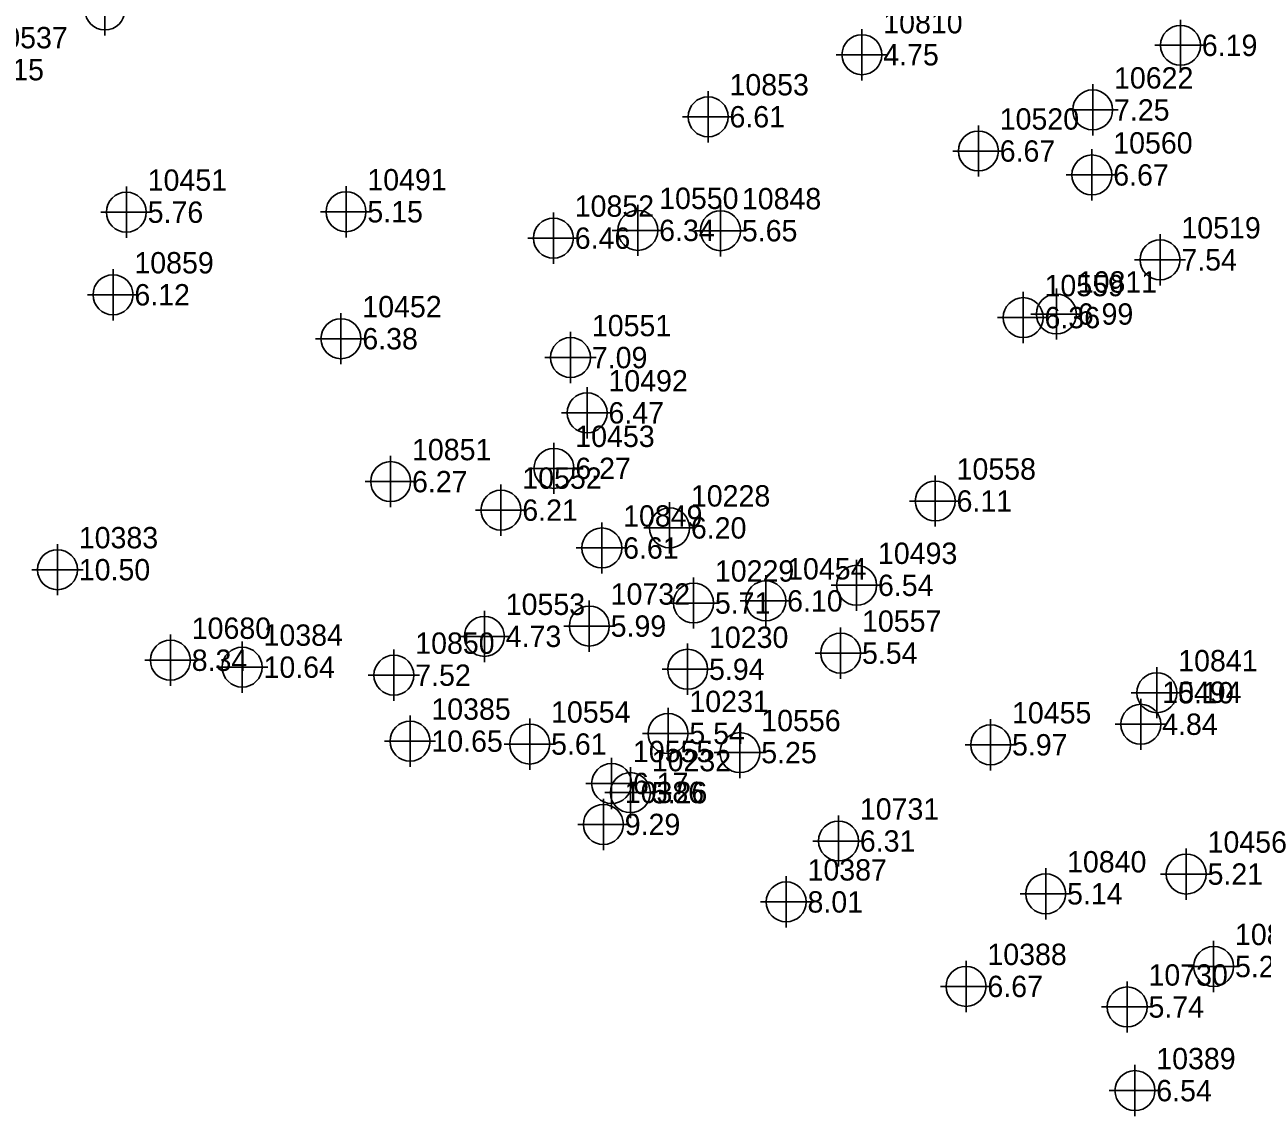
# Model space of a CAD drawing. Extents: x 2062781 to 2066835, y 358981 to 366501.
# Drawn here: x 2064858.6 to 2065003.6, y 361578.1 to 361705.9 of the extents above; entities that cross this region are included whole.
import ezdxf

# ---------------------------------------------------------------- set-up
doc = ezdxf.new("R2010")
doc.units = 0
for name, color, linetype in [('COGO Default Point Elevation', 7, 'Continuous'), ('COGO Default Point Number', 7, 'Continuous'), ('Exist DTM Regular Point Underwater CELL', 7, 'Continuous')]:
    doc.layers.add(name, color=color, linetype=linetype)

msp = doc.modelspace()

# ---------------------------------------------------------------- linework, layer by layer
at = {"layer": 'Exist DTM Regular Point Underwater CELL'}
for points in [[(2064867.99, 361707.64), (2064867.99, 361704.64)], [(2064993.98, 361706.5), (2064993.98, 361703.5)], [(2064956.66, 361705.4), (2064956.66, 361702.4)], [(2064990.98, 361703.5), (2064993.98, 361703.5)], [(2064993.98, 361703.5), (2064996.98, 361703.5)], [(2064993.98, 361703.5), (2064993.98, 361700.5)], [(2064953.66, 361702.4), (2064956.66, 361702.4)], [(2064956.66, 361702.4), (2064959.66, 361702.4)], [(2064956.66, 361702.4), (2064956.66, 361699.4)], [(2064983.69, 361698.94), (2064983.69, 361695.94)], [(2064938.65, 361698.13), (2064938.65, 361695.13)], [(2064980.69, 361695.94), (2064983.69, 361695.94)], [(2064983.69, 361695.94), (2064986.69, 361695.94)], [(2064983.69, 361695.94), (2064983.69, 361692.94)], [(2064935.65, 361695.13), (2064938.65, 361695.13)], [(2064938.65, 361695.13), (2064941.65, 361695.13)], [(2064938.65, 361695.13), (2064938.65, 361692.13)], [(2064970.3, 361694.13), (2064970.3, 361691.13)], [(2064967.3, 361691.13), (2064970.3, 361691.13)], [(2064970.3, 361691.13), (2064973.3, 361691.13)], [(2064970.3, 361691.13), (2064970.3, 361688.13)], [(2064983.6, 361691.33), (2064983.6, 361688.33)], [(2064980.6, 361688.33), (2064983.6, 361688.33)], [(2064983.6, 361688.33), (2064986.6, 361688.33)], [(2064983.6, 361688.33), (2064983.6, 361685.33)], [(2064870.5, 361686.97), (2064870.5, 361683.97)], [(2064896.23, 361687.02), (2064896.23, 361684.02)], [(2064930.41, 361684.84), (2064930.41, 361681.84)], [(2064940.1, 361684.8), (2064940.1, 361681.8)], [(2064867.5, 361683.97), (2064870.5, 361683.97)], [(2064870.5, 361683.97), (2064873.5, 361683.97)], [(2064870.5, 361683.97), (2064870.5, 361680.97)], [(2064893.23, 361684.02), (2064896.23, 361684.02)], [(2064896.23, 361684.02), (2064899.23, 361684.02)], [(2064896.23, 361684.02), (2064896.23, 361681.02)], [(2064920.52, 361683.93), (2064920.52, 361680.93)], [(2064927.41, 361681.84), (2064930.41, 361681.84)], [(2064930.41, 361681.84), (2064933.41, 361681.84)], [(2064930.41, 361681.84), (2064930.41, 361678.84)], [(2064937.1, 361681.8), (2064940.1, 361681.8)], [(2064940.1, 361681.8), (2064943.1, 361681.8)], [(2064940.1, 361681.8), (2064940.1, 361678.8)], [(2064917.52, 361680.93), (2064920.52, 361680.93)], [(2064920.52, 361680.93), (2064923.52, 361680.93)], [(2064920.52, 361680.93), (2064920.52, 361677.93)], [(2064991.58, 361681.39), (2064991.58, 361678.39)], [(2064868.94, 361677.3), (2064868.94, 361674.3)], [(2064988.58, 361678.39), (2064991.58, 361678.39)], [(2064991.58, 361678.39), (2064994.58, 361678.39)], [(2064991.58, 361678.39), (2064991.58, 361675.39)], [(2064865.94, 361674.3), (2064868.94, 361674.3)], [(2064868.94, 361674.3), (2064871.94, 361674.3)], [(2064868.94, 361674.3), (2064868.94, 361671.3)], [(2064975.55, 361674.63), (2064975.55, 361671.63)], [(2064979.44, 361675.05), (2064979.44, 361672.05)], [(2064895.64, 361672.16), (2064895.64, 361669.16)], [(2064972.55, 361671.63), (2064975.55, 361671.63)], [(2064975.55, 361671.63), (2064978.55, 361671.63)], [(2064975.55, 361671.63), (2064975.55, 361668.63)], [(2064976.44, 361672.05), (2064979.44, 361672.05)], [(2064979.44, 361672.05), (2064982.44, 361672.05)], [(2064979.44, 361672.05), (2064979.44, 361669.05)], [(2064922.53, 361669.95), (2064922.53, 361666.95)], [(2064892.64, 361669.16), (2064895.64, 361669.16)], [(2064895.64, 361669.16), (2064898.64, 361669.16)], [(2064895.64, 361669.16), (2064895.64, 361666.16)], [(2064919.53, 361666.95), (2064922.53, 361666.95)], [(2064922.53, 361666.95), (2064925.53, 361666.95)], [(2064922.53, 361666.95), (2064922.53, 361663.95)], [(2064924.47, 361663.48), (2064924.47, 361660.48)], [(2064921.47, 361660.48), (2064924.47, 361660.48)], [(2064924.47, 361660.48), (2064927.47, 361660.48)], [(2064924.47, 361660.48), (2064924.47, 361657.48)], [(2064920.59, 361656.98), (2064920.59, 361653.98)], [(2064901.46, 361655.43), (2064901.46, 361652.43)], [(2064917.59, 361653.98), (2064920.59, 361653.98)], [(2064920.59, 361653.98), (2064923.59, 361653.98)], [(2064920.59, 361653.98), (2064920.59, 361650.98)], [(2064898.46, 361652.43), (2064901.46, 361652.43)], [(2064901.46, 361652.43), (2064904.46, 361652.43)], [(2064901.46, 361652.43), (2064901.46, 361649.43)], [(2064965.25, 361653.16), (2064965.25, 361650.16)], [(2064914.38, 361652.09), (2064914.38, 361649.09)], [(2064934.13, 361650.01), (2064934.13, 361647.01)], [(2064962.25, 361650.16), (2064965.25, 361650.16)], [(2064965.25, 361650.16), (2064968.25, 361650.16)], [(2064965.25, 361650.16), (2064965.25, 361647.16)], [(2064911.38, 361649.09), (2064914.38, 361649.09)], [(2064914.38, 361649.09), (2064917.38, 361649.09)], [(2064914.38, 361649.09), (2064914.38, 361646.09)], [(2064926.19, 361647.66), (2064926.19, 361644.66)], [(2064931.13, 361647.01), (2064934.13, 361647.01)], [(2064934.13, 361647.01), (2064937.13, 361647.01)], [(2064934.13, 361647.01), (2064934.13, 361644.01)], [(2064862.43, 361645.12), (2064862.43, 361642.12)], [(2064923.19, 361644.66), (2064926.19, 361644.66)], [(2064926.19, 361644.66), (2064929.19, 361644.66)], [(2064926.19, 361644.66), (2064926.19, 361641.66)], [(2064956.04, 361643.29), (2064956.04, 361640.29)], [(2064859.43, 361642.12), (2064862.43, 361642.12)], [(2064862.43, 361642.12), (2064865.43, 361642.12)], [(2064862.43, 361642.12), (2064862.43, 361639.12)], [(2064936.94, 361641.22), (2064936.94, 361638.22)], [(2064945.4, 361641.47), (2064945.4, 361638.47)], [(2064953.04, 361640.29), (2064956.04, 361640.29)], [(2064956.04, 361640.29), (2064959.04, 361640.29)], [(2064956.04, 361640.29), (2064956.04, 361637.29)], [(2064924.73, 361638.52), (2064924.73, 361635.52)], [(2064933.94, 361638.22), (2064936.94, 361638.22)], [(2064936.94, 361638.22), (2064939.94, 361638.22)], [(2064936.94, 361638.22), (2064936.94, 361635.22)], [(2064942.4, 361638.47), (2064945.4, 361638.47)], [(2064945.4, 361638.47), (2064948.4, 361638.47)], [(2064945.4, 361638.47), (2064945.4, 361635.47)], [(2064912.44, 361637.31), (2064912.44, 361634.31)], [(2064921.73, 361635.52), (2064924.73, 361635.52)], [(2064924.73, 361635.52), (2064927.73, 361635.52)], [(2064924.73, 361635.52), (2064924.73, 361632.52)], [(2064954.17, 361635.35), (2064954.17, 361632.35)], [(2064875.66, 361634.52), (2064875.66, 361631.52)], [(2064884.07, 361633.71), (2064884.07, 361630.71)], [(2064909.44, 361634.31), (2064912.44, 361634.31)], [(2064912.44, 361634.31), (2064915.44, 361634.31)], [(2064912.44, 361634.31), (2064912.44, 361631.31)], [(2064901.84, 361632.77), (2064901.84, 361629.77)], [(2064936.25, 361633.46), (2064936.25, 361630.46)], [(2064951.17, 361632.35), (2064954.17, 361632.35)], [(2064954.17, 361632.35), (2064957.17, 361632.35)], [(2064954.17, 361632.35), (2064954.17, 361629.35)], [(2064872.66, 361631.52), (2064875.66, 361631.52)], [(2064875.66, 361631.52), (2064878.66, 361631.52)], [(2064875.66, 361631.52), (2064875.66, 361628.52)], [(2064881.07, 361630.71), (2064884.07, 361630.71)], [(2064884.07, 361630.71), (2064887.07, 361630.71)], [(2064884.07, 361630.71), (2064884.07, 361627.71)], [(2064991.21, 361630.72), (2064991.21, 361627.72)], [(2064898.84, 361629.77), (2064901.84, 361629.77)], [(2064901.84, 361629.77), (2064904.84, 361629.77)], [(2064901.84, 361629.77), (2064901.84, 361626.77)], [(2064933.25, 361630.46), (2064936.25, 361630.46)], [(2064936.25, 361630.46), (2064939.25, 361630.46)], [(2064936.25, 361630.46), (2064936.25, 361627.46)], [(2064988.21, 361627.72), (2064991.21, 361627.72)], [(2064989.33, 361627.02), (2064989.33, 361624.02)], [(2064991.21, 361627.72), (2064994.21, 361627.72)], [(2064991.21, 361627.72), (2064991.21, 361624.72)], [(2064903.73, 361625.05), (2064903.73, 361622.05)], [(2064933.95, 361625.95), (2064933.95, 361622.95)], [(2064917.75, 361624.71), (2064917.75, 361621.71)], [(2064942.37, 361623.71), (2064942.37, 361620.71)], [(2064971.74, 361624.62), (2064971.74, 361621.62)], [(2064986.33, 361624.02), (2064989.33, 361624.02)], [(2064989.33, 361624.02), (2064992.33, 361624.02)], [(2064989.33, 361624.02), (2064989.33, 361621.02)], [(2064900.73, 361622.05), (2064903.73, 361622.05)], [(2064903.73, 361622.05), (2064906.73, 361622.05)], [(2064903.73, 361622.05), (2064903.73, 361619.05)], [(2064930.95, 361622.95), (2064933.95, 361622.95)], [(2064933.95, 361622.95), (2064936.95, 361622.95)], [(2064933.95, 361622.95), (2064933.95, 361619.95)], [(2064914.75, 361621.71), (2064917.75, 361621.71)], [(2064917.75, 361621.71), (2064920.75, 361621.71)], [(2064917.75, 361621.71), (2064917.75, 361618.71)], [(2064939.37, 361620.71), (2064942.37, 361620.71)], [(2064942.37, 361620.71), (2064945.37, 361620.71)], [(2064942.37, 361620.71), (2064942.37, 361617.71)], [(2064968.74, 361621.62), (2064971.74, 361621.62)], [(2064971.74, 361621.62), (2064974.74, 361621.62)], [(2064971.74, 361621.62), (2064971.74, 361618.62)], [(2064927.34, 361620.09), (2064927.34, 361617.09)], [(2064929.54, 361619.02), (2064929.54, 361616.02)], [(2064924.34, 361617.09), (2064927.34, 361617.09)], [(2064927.34, 361617.09), (2064930.34, 361617.09)], [(2064927.34, 361617.09), (2064927.34, 361614.09)], [(2064926.38, 361615.3), (2064926.38, 361612.3)], [(2064926.54, 361616.02), (2064929.54, 361616.02)], [(2064929.54, 361616.02), (2064932.54, 361616.02)], [(2064929.54, 361616.02), (2064929.54, 361613.02)], [(2064953.92, 361613.36), (2064953.92, 361610.36)], [(2064923.38, 361612.3), (2064926.38, 361612.3)], [(2064926.38, 361612.3), (2064929.38, 361612.3)], [(2064926.38, 361612.3), (2064926.38, 361609.3)], [(2064950.92, 361610.36), (2064953.92, 361610.36)], [(2064953.92, 361610.36), (2064956.92, 361610.36)], [(2064953.92, 361610.36), (2064953.92, 361607.36)], [(2064994.65, 361609.49), (2064994.65, 361606.49)], [(2064947.79, 361606.23), (2064947.79, 361603.23)], [(2064978.19, 361607.18), (2064978.19, 361604.18)], [(2064991.65, 361606.49), (2064994.65, 361606.49)], [(2064994.65, 361606.49), (2064997.65, 361606.49)], [(2064994.65, 361606.49), (2064994.65, 361603.49)], [(2064944.79, 361603.23), (2064947.79, 361603.23)], [(2064947.79, 361603.23), (2064950.79, 361603.23)], [(2064947.79, 361603.23), (2064947.79, 361600.23)], [(2064975.19, 361604.18), (2064978.19, 361604.18)], [(2064978.19, 361604.18), (2064981.19, 361604.18)], [(2064978.19, 361604.18), (2064978.19, 361601.18)], [(2064997.86, 361598.67), (2064997.86, 361595.67)], [(2064968.86, 361596.34), (2064968.86, 361593.34)], [(2064994.86, 361595.67), (2064997.86, 361595.67)], [(2064997.86, 361595.67), (2065000.86, 361595.67)], [(2064997.86, 361595.67), (2064997.86, 361592.67)], [(2064965.86, 361593.34), (2064968.86, 361593.34)], [(2064968.86, 361593.34), (2064971.86, 361593.34)], [(2064968.86, 361593.34), (2064968.86, 361590.34)], [(2064987.73, 361593.93), (2064987.73, 361590.93)], [(2064984.73, 361590.93), (2064987.73, 361590.93)], [(2064987.73, 361590.93), (2064990.73, 361590.93)], [(2064987.73, 361590.93), (2064987.73, 361587.93)], [(2064988.64, 361584.14), (2064988.64, 361581.14)], [(2064985.64, 361581.14), (2064988.64, 361581.14)], [(2064988.64, 361581.14), (2064991.64, 361581.14)], [(2064988.64, 361581.14), (2064988.64, 361578.14)]]:
    msp.add_lwpolyline(points, dxfattribs=at)
for centre in [(2064867.99, 361707.64), (2064956.66, 361702.4), (2064993.98, 361703.5), (2064938.65, 361695.13), (2064983.69, 361695.94), (2064970.3, 361691.13), (2064983.6, 361688.33), (2064870.5, 361683.97), (2064896.23, 361684.02), (2064920.52, 361680.93), (2064930.41, 361681.84), (2064940.1, 361681.8), (2064991.58, 361678.39), (2064868.94, 361674.3), (2064979.44, 361672.05), (2064975.55, 361671.63), (2064895.64, 361669.16), (2064922.53, 361666.95), (2064924.47, 361660.48), (2064920.59, 361653.98), (2064901.46, 361652.43), (2064965.25, 361650.16), (2064914.38, 361649.09), (2064934.13, 361647.01), (2064926.19, 361644.66), (2064862.43, 361642.12), (2064956.04, 361640.29), (2064936.94, 361638.22), (2064945.4, 361638.47), (2064912.44, 361634.31), (2064924.73, 361635.52), (2064875.66, 361631.52), (2064954.17, 361632.35), (2064884.07, 361630.71), (2064936.25, 361630.46), (2064901.84, 361629.77), (2064991.21, 361627.72), (2064989.33, 361624.02), (2064933.95, 361622.95), (2064903.73, 361622.05), (2064917.75, 361621.71), (2064971.74, 361621.62), (2064942.37, 361620.71), (2064927.34, 361617.09), (2064929.54, 361616.02), (2064926.38, 361612.3), (2064953.92, 361610.36), (2064994.65, 361606.49), (2064978.19, 361604.18), (2064947.79, 361603.23), (2064997.86, 361595.67), (2064968.86, 361593.34), (2064987.73, 361590.93), (2064988.64, 361581.14)]:
    msp.add_circle(centre, 2.34, dxfattribs=at)

# ---------------------------------------------------------------- texts
at = {"layer": 'COGO Default Point Elevation'}
for s, p in [('6.19', (2064996.48, 361702.25)), ('4.75', (2064959.16, 361701.15)), ('5.15', (2064854.34, 361699.4)), ('6.61', (2064941.15, 361693.89)), ('7.25', (2064986.19, 361694.69)), ('6.67', (2064972.8, 361689.88)), ('6.67', (2064986.1, 361687.08)), ('5.76', (2064873, 361682.72)), ('5.15', (2064898.73, 361682.77)), ('6.34', (2064932.91, 361680.59)), ('5.65', (2064942.6, 361680.55)), ('6.46', (2064923.02, 361679.68)), ('7.54', (2064994.08, 361677.14)), ('6.12', (2064871.44, 361673.05)), ('6.36', (2064978.05, 361670.38)), ('6.99', (2064981.94, 361670.8)), ('6.38', (2064898.14, 361667.91)), ('7.09', (2064925.03, 361665.7)), ('6.47', (2064926.97, 361659.23)), ('6.27', (2064923.09, 361652.73)), ('6.27', (2064903.96, 361651.18)), ('6.11', (2064967.75, 361648.91)), ('6.21', (2064916.88, 361647.84)), ('6.20', (2064936.63, 361645.76)), ('6.61', (2064928.69, 361643.41)), ('10.50', (2064864.93, 361640.87)), ('6.54', (2064958.54, 361639.04)), ('5.71', (2064939.44, 361636.97)), ('6.10', (2064947.9, 361637.22)), ('5.99', (2064927.23, 361634.27)), ('4.73', (2064914.94, 361633.07)), ('5.54', (2064956.67, 361631.1)), ('8.34', (2064878.16, 361630.27)), ('10.64', (2064886.57, 361629.46)), ('7.52', (2064904.34, 361628.52)), ('5.94', (2064938.75, 361629.21)), ('5.10', (2064993.71, 361626.47)), ('4.84', (2064991.83, 361622.78)), ('5.54', (2064936.45, 361621.7)), ('10.65', (2064906.23, 361620.8)), ('5.61', (2064920.25, 361620.46)), ('5.25', (2064944.87, 361619.46)), ('5.97', (2064974.24, 361620.37)), ('6.17', (2064929.84, 361615.84)), ('5.26', (2064932.04, 361614.77)), ('9.29', (2064928.88, 361611.05)), ('6.31', (2064956.42, 361609.11)), ('5.21', (2064997.15, 361605.24)), ('5.14', (2064980.69, 361602.93)), ('8.01', (2064950.29, 361601.98)), ('5.22', (2065000.36, 361594.42)), ('6.67', (2064971.36, 361592.09)), ('5.74', (2064990.23, 361589.68)), ('6.54', (2064991.14, 361579.89))]:
    msp.add_text(s, height=2.5, dxfattribs=at).set_placement(p)
at = {"layer": 'COGO Default Point Number'}
for s, p in [('10810', (2064959.16, 361704.9)), ('10537', (2064854.34, 361703.15)), ('10622', (2064986.19, 361698.44)), ('10853', (2064941.15, 361697.64)), ('10520', (2064972.8, 361693.63)), ('10560', (2064986.1, 361690.83)), ('10451', (2064873, 361686.47)), ('10491', (2064898.73, 361686.52)), ('10852', (2064923.02, 361683.43)), ('10550', (2064932.91, 361684.34)), ('10848', (2064942.6, 361684.3)), ('10519', (2064994.08, 361680.89)), ('10859', (2064871.44, 361676.8)), ('10811', (2064981.94, 361674.55)), ('10559', (2064978.05, 361674.13)), ('10452', (2064898.14, 361671.66)), ('10551', (2064925.03, 361669.45)), ('10492', (2064926.97, 361662.98)), ('10453', (2064923.09, 361656.48)), ('10851', (2064903.96, 361654.93)), ('10552', (2064916.88, 361651.59)), ('10558', (2064967.75, 361652.66)), ('10228', (2064936.63, 361649.51)), ('10849', (2064928.69, 361647.16)), ('10383', (2064864.93, 361644.62)), ('10493', (2064958.54, 361642.79)), ('10229', (2064939.44, 361640.72)), ('10454', (2064947.9, 361640.97)), ('10732', (2064927.23, 361638.02)), ('10553', (2064914.94, 361636.82)), ('10680', (2064878.16, 361634.02)), ('10557', (2064956.67, 361634.85)), ('10384', (2064886.57, 361633.21)), ('10230', (2064938.75, 361632.96)), ('10850', (2064904.34, 361632.27)), ('10841', (2064993.71, 361630.22)), ('10231', (2064936.45, 361625.45)), ('10494', (2064991.83, 361626.53)), ('10385', (2064906.23, 361624.55)), ('10554', (2064920.25, 361624.21)), ('10455', (2064974.24, 361624.12)), ('10556', (2064944.87, 361623.21)), ('10555', (2064929.84, 361619.59)), ('10232', (2064932.04, 361618.52)), ('10386', (2064928.88, 361614.8)), ('10731', (2064956.42, 361612.86)), ('10456', (2064997.15, 361608.99)), ('10840', (2064980.69, 361606.68)), ('10387', (2064950.29, 361605.73)), ('10839', (2065000.36, 361598.17)), ('10388', (2064971.36, 361595.84)), ('10730', (2064990.23, 361593.43)), ('10389', (2064991.14, 361583.64))]:
    msp.add_text(s, height=2.5, dxfattribs=at).set_placement(p)

doc.saveas('drawing.dxf')
